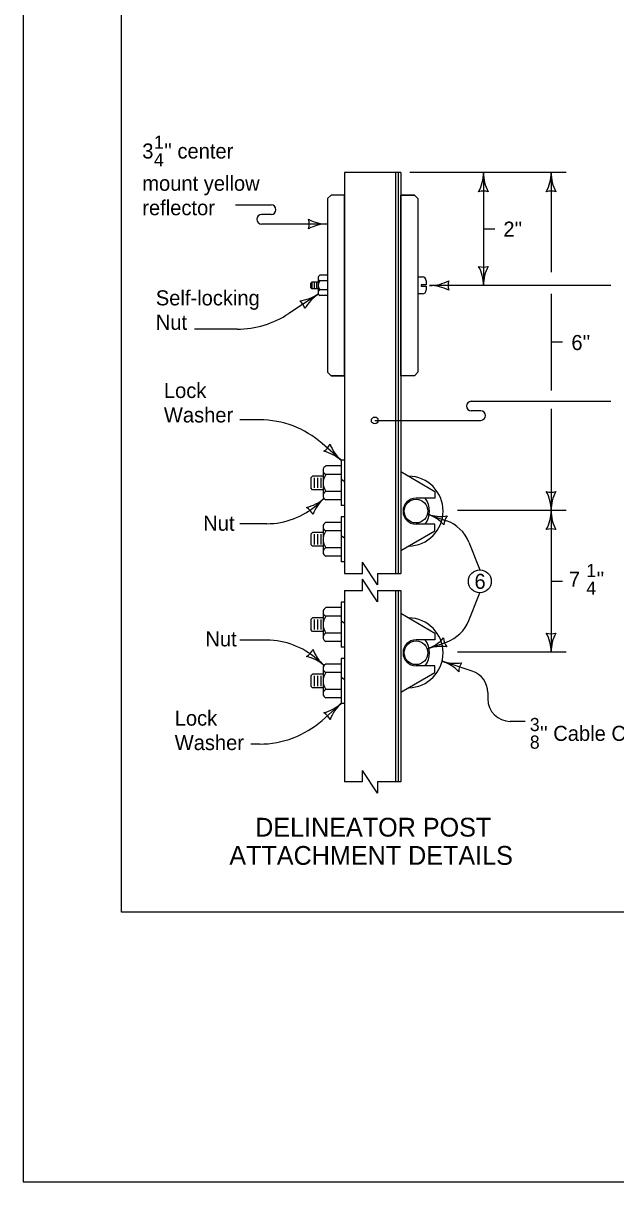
# Model space of a CAD drawing. Extents: x 228 to 3572, y -1307 to 1277.
# Drawn here: x 228 to 858, y -1307 to -75 of the extents above; entities that cross this region are included whole.
import ezdxf

# ---------------------------------------------------------------- set-up
doc = ezdxf.new("R2010")
doc.units = 0
for name, color, linetype in [('dsnShtPlotShapeBatchPrint', 7, 'Continuous'), ('dsnStdBorder', 7, 'Continuous'), ('dsnStdDimension', 7, 'Continuous'), ('Level 2', 7, 'Continuous'), ('Level 3', 7, 'Continuous')]:
    doc.layers.add(name, color=color, linetype=linetype)

msp = doc.modelspace()

# ---------------------------------------------------------------- linework, layer by layer
at = {"layer": 'dsnShtPlotShapeBatchPrint'}
msp.add_lwpolyline([(228, -1307), (3572, -1307), (3572, 1277), (228, 1277)], close=True, dxfattribs=at)
at = {"layer": 'dsnStdBorder'}
msp.add_lwpolyline([(332.5, 990), (3467.5, 990), (3467.5, -1020), (332.5, -1020)], close=True, dxfattribs=at)
at = {"layer": 'dsnStdDimension'}
for p, q in [((805.6, -233.6), (639.3, -233.6)), ((717.6, -233.6), (717.6, -353.6)), ((789.6, -233.6), (789.6, -339.5)), ((453.7, -267.9), (491.8, -267.9)), ((491.8, -278.1), (481.6, -278.1)), ((481.6, -288.2), (551.9, -288.2)), ((729.6, -293.6), (717.6, -293.6)), ((853.3, -353.6), (660.4, -353.6)), ((541.9, -362.8), (510.7, -383.4)), ((789.6, -362.6), (789.6, -465.3)), ((455.5, -400), (410.3, -400)), ((801.6, -414), (789.6, -414)), ((704.6, -476.8), (853.3, -476.8)), ((714.8, -487), (704.6, -487)), ((789.6, -484.7), (789.6, -593)), ((479.6, -496.5), (458.3, -496.5)), ((602, -497.1), (714.8, -497.1)), ((566.3, -539.6), (546, -521.7)), ((658.1, -596.7), (678.2, -603.8)), ((805.6, -593), (689.9, -593)), ((789.6, -593), (789.6, -743.6)), ((487.2, -607), (458.3, -607)), ((702.1, -626.7), (713.8, -656.1)), ((801.6, -668.3), (789.6, -668.3)), ((702.1, -710), (713.8, -680.6)), ((487.2, -730.9), (458.3, -730.9)), ((657.8, -740.1), (678.2, -732.9)), ((805.6, -743.6), (689.9, -743.6)), ((705.7, -763.8), (673.6, -753.3)), ((722.2, -786.6), (722.2, -793.3)), ((566.3, -798.3), (546, -816.2)), ((761.9, -817.3), (746.2, -817.3)), ((479.6, -841.4), (470.3, -841.4))]:
    msp.add_line(p, q, dxfattribs=at)
msp.add_circle((602, -497.1), 3.56, dxfattribs=at)
for centre, radius, start, end in [((674.4, -233.6), 43.2, 331.9275, 0), ((760.8, -233.6), 43.2, 180, 208.0725), ((746.4, -233.6), 43.2, 331.9275, 0), ((832.8, -233.6), 43.2, 180, 208.0725), ((717.6, -269.9), 16.7, 72.2666, 107.7334), ((789.6, -269.9), 16.7, 72.2666, 107.7334), ((491.8, -273), 5.08, 270, 90), ((481.6, -283.2), 5.08, 90, 270), ((515.7, -288.2), 16.7, 342.2666, 17.7333), ((551.9, -245.1), 43.2, 241.9275, 270), ((551.9, -331.4), 43.2, 90, 118.0725), ((717.6, -317.4), 16.7, 252.2666, 287.7333), ((674.4, -353.6), 43.2, 0, 28.0725), ((760.8, -353.6), 43.2, 151.9275, 180), ((660.4, -310.5), 43.2, 270, 298.0725), ((660.4, -396.8), 43.2, 61.9275, 90), ((696.7, -353.6), 16.7, 162.2666, 197.7334), ((518.1, -326.8), 43.2, 275.4176, 303.4901), ((565.8, -398.8), 43.2, 123.4901, 151.5626), ((511.7, -382.8), 16.7, 15.7567, 51.2234), ((455.5, -300), 100, 270, 303.49), ((704.6, -481.9), 5.08, 90, 270), ((714.8, -492), 5.08, 270, 90), ((479.6, -596.5), 100, 48.4219, 90), ((539.2, -515.6), 16.7, 300.6907, 336.1574), ((594.9, -507.3), 43.2, 200.3516, 228.4241), ((537.6, -572), 43.2, 48.4241, 76.4966), ((789.6, -556.8), 16.7, 252.2666, 287.7333), ((746.4, -593), 43.2, 0, 28.0725), ((832.8, -593), 43.2, 151.9275, 180), ((487.2, -527), 80, 270, 311.5335), ((519.4, -547.7), 43.2, 283.4664, 311.5389), ((520.9, -604), 16.7, 23.8055, 59.2722), ((576.6, -612.4), 43.2, 131.5389, 159.6114), ((672.5, -556), 43.2, 250.6038, 278.6762), ((643.8, -637.5), 43.2, 42.5313, 70.6038), ((692.3, -608.8), 16.7, 142.8704, 178.3371), ((665, -641.6), 40, 21.7823, 70.598), ((746.4, -593), 43.2, 331.9275, 0), ((832.8, -593), 43.2, 180, 208.0725), ((789.6, -629.2), 16.7, 72.2666, 107.7334), ((665, -695.1), 40, 289.4026, 338.2139), ((789.6, -707.4), 16.7, 252.2666, 287.7333), ((746.4, -743.6), 43.2, 0, 28.0725), ((832.8, -743.6), 43.2, 151.9275, 180), ((487.2, -810.9), 80, 48.4665, 90), ((643.4, -699.3), 43.2, 289.3973, 317.4697), ((672.1, -780.8), 43.2, 81.3248, 109.3973), ((691.9, -728), 16.7, 181.6639, 217.1306), ((520.9, -733.9), 16.7, 300.7278, 336.1945), ((519.4, -790.2), 43.2, 48.4611, 76.5336), ((576.6, -725.5), 43.2, 200.3886, 228.4611), ((687, -712.3), 43.2, 251.8959, 279.9683), ((660.2, -794.3), 43.2, 43.8234, 71.8959), ((708, -764.6), 16.7, 144.1625, 179.6292), ((698.2, -786.6), 24, 0, 71.8983), ((537.6, -766), 43.2, 283.5034, 311.5759), ((594.9, -830.6), 43.2, 131.5759, 159.6484), ((746.2, -793.3), 24, 180, 270), ((539.2, -822.3), 16.7, 23.8426, 59.3093), ((479.6, -741.4), 100, 270, 311.5781)]:
    msp.add_arc(centre, radius, start, end, dxfattribs=at)
at = {"layer": 'Level 2'}
for p, q in [((569.9, -233.6), (569.9, -660)), ((629.9, -233.6), (569.9, -233.6)), ((623.9, -233.6), (623.9, -660)), ((626.9, -233.6), (626.9, -660)), ((629.9, -233.6), (629.9, -660)), ((555.5, -257.6), (551.9, -261.2)), ((569.9, -257.6), (555.5, -257.6)), ((644.3, -257.6), (629.9, -257.6)), ((644.3, -257.6), (647.9, -261.2)), ((551.9, -261.2), (551.9, -446)), ((647.9, -261.2), (647.9, -446)), ((551.9, -342.8), (543.5, -342.8)), ((647.9, -344.6), (652.8, -344.6)), ((535.1, -350), (533.6, -351.5)), ((533.6, -351.5), (533.6, -355.7)), ((535.1, -357.2), (533.6, -355.7)), ((541.7, -350), (535.1, -350)), ((535.1, -350.6), (535.1, -356.6)), ((541.7, -357.2), (535.1, -357.2)), ((537.5, -350.6), (537.5, -356.6)), ((539.9, -350.6), (539.9, -356.6)), ((541.7, -345.8), (541.7, -348.8)), ((541.7, -348.8), (541.7, -358.4)), ((551.9, -348.8), (543.5, -348.8)), ((656.8, -352.9), (651.5, -352.9)), ((651.5, -352.9), (651.5, -354.4)), ((651.5, -354.4), (656.8, -354.4)), ((656.8, -348.6), (656.8, -352.9)), ((656.8, -354.4), (656.8, -358.6)), ((541.7, -358.4), (541.7, -361.4)), ((551.9, -358.4), (543.5, -358.4)), ((551.9, -364.4), (543.5, -364.4)), ((652.8, -362.6), (647.9, -362.6)), ((555.5, -449.6), (551.9, -446)), ((569.9, -449.6), (555.5, -449.6)), ((644.3, -449.6), (629.9, -449.6)), ((644.3, -449.6), (647.9, -446)), ((566.3, -539.6), (566.3, -587.6)), ((569.9, -539.6), (566.3, -539.6)), ((547.1, -552), (547.1, -575.3)), ((566.3, -545.6), (550.1, -545.6)), ((629.9, -551.6), (665.9, -572.6)), ((533.9, -558.2), (535.7, -556.4)), ((533.9, -558.2), (533.9, -569)), ((547.1, -556.4), (535.7, -556.4)), ((537.5, -558.2), (537.5, -569)), ((541.1, -558.2), (541.1, -569)), ((544.7, -558.2), (544.7, -569)), ((566.3, -554.6), (550.1, -554.6)), ((566.3, -559.4), (569.9, -562.2)), ((535.7, -570.8), (533.9, -569)), ((547.1, -570.8), (535.7, -570.8)), ((566.3, -572.6), (550.1, -572.6)), ((665.9, -572.6), (665.9, -579.8)), ((548, -580), (540.3, -586.9)), ((566.3, -581.6), (550.1, -581.6)), ((569.9, -587.6), (566.3, -587.6)), ((665.9, -579.8), (645.9, -579.8)), ((566.3, -599.6), (566.3, -647.6)), ((569.9, -599.6), (566.3, -599.6)), ((547.1, -609.8), (547.1, -636.7)), ((566.3, -605.6), (550.1, -605.6)), ((566.3, -614.6), (550.1, -614.6)), ((629.9, -635.6), (665.9, -614.6)), ((665.9, -607.4), (645.9, -607.4)), ((665.9, -614.6), (665.9, -607.4)), ((535.7, -616.4), (533.9, -618.2)), ((533.9, -618.2), (533.9, -629)), ((547.1, -616.4), (535.7, -616.4)), ((537.5, -618.2), (537.5, -629)), ((541.1, -618.2), (541.1, -629)), ((544.7, -618.2), (544.7, -629)), ((566.3, -619.4), (569.9, -622.2)), ((533.9, -629), (535.7, -630.8)), ((547.1, -630.8), (535.7, -630.8)), ((566.3, -632.6), (550.1, -632.6)), ((566.3, -641.6), (550.1, -641.6)), ((569.9, -647.6), (566.3, -647.6)), ((588.9, -660), (588.9, -648)), ((604.9, -672), (588.9, -648)), ((569.9, -660), (588.9, -660)), ((604.9, -660), (629.9, -660)), ((604.9, -660), (604.9, -672)), ((588.9, -678), (588.9, -666)), ((604.9, -690), (588.9, -666)), ((569.9, -678), (569.9, -881.6)), ((569.9, -678), (588.9, -678)), ((604.9, -678), (629.9, -678)), ((604.9, -678), (604.9, -690)), ((623.9, -678), (623.9, -881.6)), ((626.9, -678), (626.9, -881.6)), ((629.9, -678), (629.9, -881.6)), ((566.3, -696.3), (550.1, -696.3)), ((566.3, -690.3), (566.3, -738.3)), ((569.9, -690.3), (566.3, -690.3)), ((629.9, -702.3), (665.9, -723.3)), ((533.9, -708.9), (535.7, -707.1)), ((533.9, -708.9), (533.9, -719.7)), ((547.1, -707.1), (535.7, -707.1)), ((537.5, -708.9), (537.5, -719.7)), ((541.1, -708.9), (541.1, -719.7)), ((544.7, -708.9), (544.7, -719.7)), ((547.1, -702.6), (547.1, -725.9)), ((566.3, -705.3), (550.1, -705.3)), ((566.3, -710), (569.9, -712.8)), ((535.7, -721.5), (533.9, -719.7)), ((547.1, -721.5), (535.7, -721.5)), ((566.3, -723.3), (550.1, -723.3)), ((665.9, -723.3), (665.9, -730.5)), ((566.3, -732.3), (550.1, -732.3)), ((569.9, -738.3), (566.3, -738.3)), ((665.9, -730.5), (645.9, -730.5)), ((548, -757.9), (540.3, -751)), ((566.3, -750.3), (566.3, -798.3)), ((569.9, -750.3), (566.3, -750.3)), ((547.1, -760.4), (547.1, -787.3)), ((566.3, -756.3), (550.1, -756.3)), ((665.9, -758.1), (645.9, -758.1)), ((665.9, -765.3), (665.9, -758.1)), ((535.7, -767.1), (533.9, -768.9)), ((533.9, -768.9), (533.9, -779.7)), ((547.1, -767.1), (535.7, -767.1)), ((537.5, -768.9), (537.5, -779.7)), ((541.1, -768.9), (541.1, -779.7)), ((544.7, -768.9), (544.7, -779.7)), ((566.3, -765.3), (550.1, -765.3)), ((566.3, -770), (569.9, -772.8)), ((629.9, -786.3), (665.9, -765.3)), ((533.9, -779.7), (535.7, -781.5)), ((547.1, -781.5), (535.7, -781.5)), ((566.3, -783.3), (550.1, -783.3)), ((566.3, -792.3), (550.1, -792.3)), ((569.9, -798.3), (566.3, -798.3)), ((588.9, -881.6), (588.9, -869.6)), ((604.9, -893.6), (588.9, -869.6)), ((588.9, -881.6), (569.9, -881.6)), ((604.9, -881.6), (604.9, -893.6)), ((629.9, -881.6), (604.9, -881.6))]:
    msp.add_line(p, q, dxfattribs=at)
for points in [[(569.9, -449.6), (569.9, -257.6), (555.5, -257.6), (551.9, -261.2), (551.9, -446), (555.5, -449.6)], [(629.9, -449.6), (629.9, -257.6), (644.3, -257.6), (647.9, -261.2), (647.9, -446), (644.3, -449.6)]]:
    msp.add_lwpolyline(points, close=True, dxfattribs=at)
for centre, radius in [((645.9, -593.6), 12.6), ((713.8, -668.3), 12.2), ((645.9, -744.3), 12.6)]:
    msp.add_circle(centre, radius, dxfattribs=at)
for centre, radius, start, end in [((545.1, -345.8), 3.4, 118.0725, 241.9275), ((652.8, -348.6), 4, 0, 90), ((549, -353.6), 7.3, 138.8879, 221.1121), ((545.1, -361.4), 3.4, 118.0725, 241.9275), ((652.8, -358.6), 4, 270, 0), ((551.9, -550.1), 4.87, 112.6199, 247.3801), ((562.1, -563.6), 15, 143.1301, 216.8699), ((637.5, -593.6), 37.2, 270.9366, 89.0634), ((551.9, -577.1), 4.87, 112.6199, 247.3801), ((645.9, -593.6), 13.8, 90, 270), ((637.5, -593.6), 22.8, 322.7522, 37.2478), ((551.9, -610.1), 4.87, 112.6199, 247.3801), ((562.1, -623.6), 15, 143.1301, 216.8699), ((551.9, -637.1), 4.87, 112.6199, 247.3801), ((551.9, -700.8), 4.87, 112.6199, 247.3801), ((562.1, -714.3), 15, 143.1301, 216.8699), ((637.5, -744.3), 37.2, 270.9366, 89.0634), ((551.9, -727.8), 4.87, 112.6199, 247.3801), ((645.9, -744.3), 13.8, 90, 270), ((637.5, -744.3), 22.8, 322.7522, 37.2478), ((551.9, -760.8), 4.87, 112.6199, 247.3801), ((562.1, -774.3), 15, 143.1301, 216.8699), ((551.9, -787.8), 4.87, 112.6199, 247.3801)]:
    msp.add_arc(centre, radius, start, end, dxfattribs=at)

# ---------------------------------------------------------------- texts
at = {"layer": 'dsnStdDimension'}
for s, height, p in [('1', 14, (367.1, -208.2)), ('3', 16, (354.7, -218.6)), ("'' center", 16, (378, -218.6)), ('4', 14, (367.1, -226.9)), ('mount yellow', 16, (354.7, -252.9)), ('reflector', 16, (354.7, -278.9)), ("2''", 16, (738.8, -301.7)), ('Self-locking ', 16, (369.1, -374.8)), ('Nut', 16, (369.1, -400.8)), ("6''", 16, (811.2, -422.3)), ('Lock ', 16, (377.7, -473.3)), ('Washer', 16, (377.7, -499.3)), ('Nut', 16, (419.5, -614.5)), ('1', 14, (827.1, -663.8)), ('7 ', 16, (808.5, -674.1)), ("''", 16, (838, -674.1)), ('4', 14, (827.1, -682.5)), ('Nut', 16, (421.8, -737.5)), ('Lock ', 16, (389.2, -821.8)), ('3', 14, (767, -827.6)), ("'' Cable Clamp", 16, (777.8, -838)), ('Washer', 16, (389.2, -847.8)), ('8', 14, (767, -846.3))]:
    msp.add_text(s, height=height, dxfattribs=at).set_placement(p)
at = {"layer": 'Level 3'}
for s, height, p in [('6', 16, (708.1, -676.3)), ('DELINEATOR POST', 20, (474.8, -939.8)), ('ATTACHMENT DETAILS', 20, (447.3, -969.8))]:
    msp.add_text(s, height=height, dxfattribs=at).set_placement(p)

doc.saveas('drawing.dxf')
